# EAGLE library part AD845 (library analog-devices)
Precision, 16 MHz CBFET Op Amp Source: http://www.analog.com/static/imported-files/data_sheets/AD845.pdf
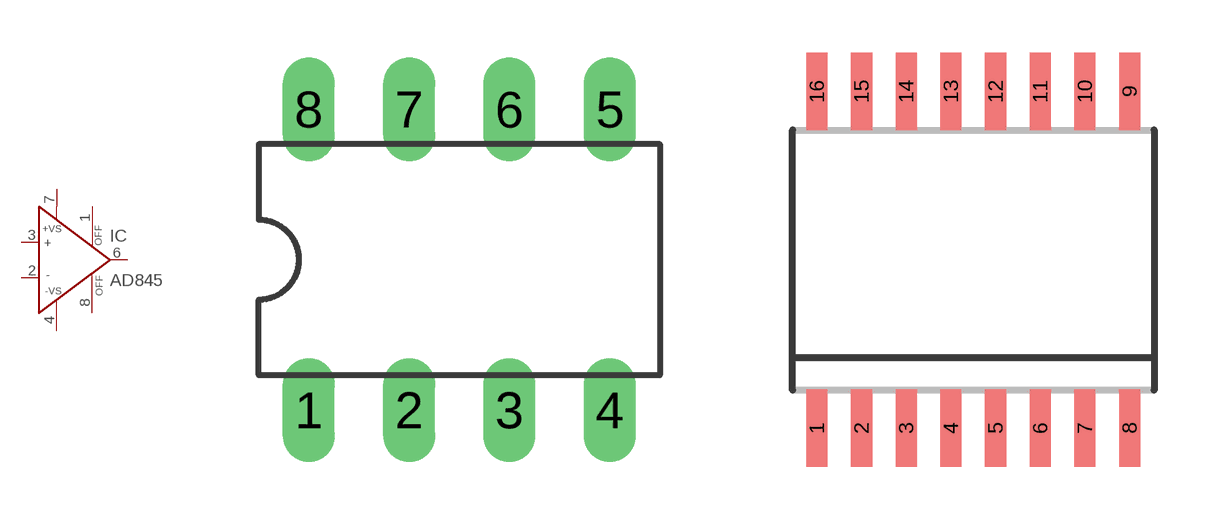
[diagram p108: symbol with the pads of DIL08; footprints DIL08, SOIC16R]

Designator prefix IC

## AD845N (MF: ALTERA CORPORATION; MPN: AD845KNZ; OC_FARNELL: 9605649; OC_NEWARK: 59K6757)  [DIL08]
1  OFF  pas
2  IN-  in
3  IN+  in
4  -VS  in
6  OUT  out
7  +VS  in
8  OFF  pas

## AD845R16 (MF: ALTERA CORPORATION; MPN: AD845JR-16; OC_FARNELL: unknown; OC_NEWARK: 05F7719)  [SOIC16R]
3  OFF  pas
4  IN-  in
5  IN+  in
6  -VS  in
12  OUT  out
13  +VS  in
14  OFF  pas

## Footprint DIL08 (pad centres in mm)
Dual In Line Package
drill 0.813 long: 1 -3.81,-3.81; 2 -1.27,-3.81; 3 1.27,-3.81; 4 3.81,-3.81; 5 3.81,3.81; 6 1.27,3.81; 7 -1.27,3.81; 8 -3.81,3.81

## Footprint SOIC16R (pad centres in mm)
16-Lead SOIC (R) Package Source: http://www.analog.com/static/imported-files/data_sheets/AD745.pdf
smd 0.6 x 2.2: 1 -4.445,-4.775; 2 -3.175,-4.775; 3 -1.905,-4.775; 4 -0.635,-4.775; 5 0.635,-4.775; 6 1.905,-4.775; 7 3.175,-4.775; 8 4.445,-4.775; 9 4.445,4.8; 10 3.175,4.8; 11 1.905,4.8; 12 0.635,4.8; 13 -0.635,4.8; 14 -1.905,4.8; 15 -3.175,4.8; 16 -4.445,4.8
